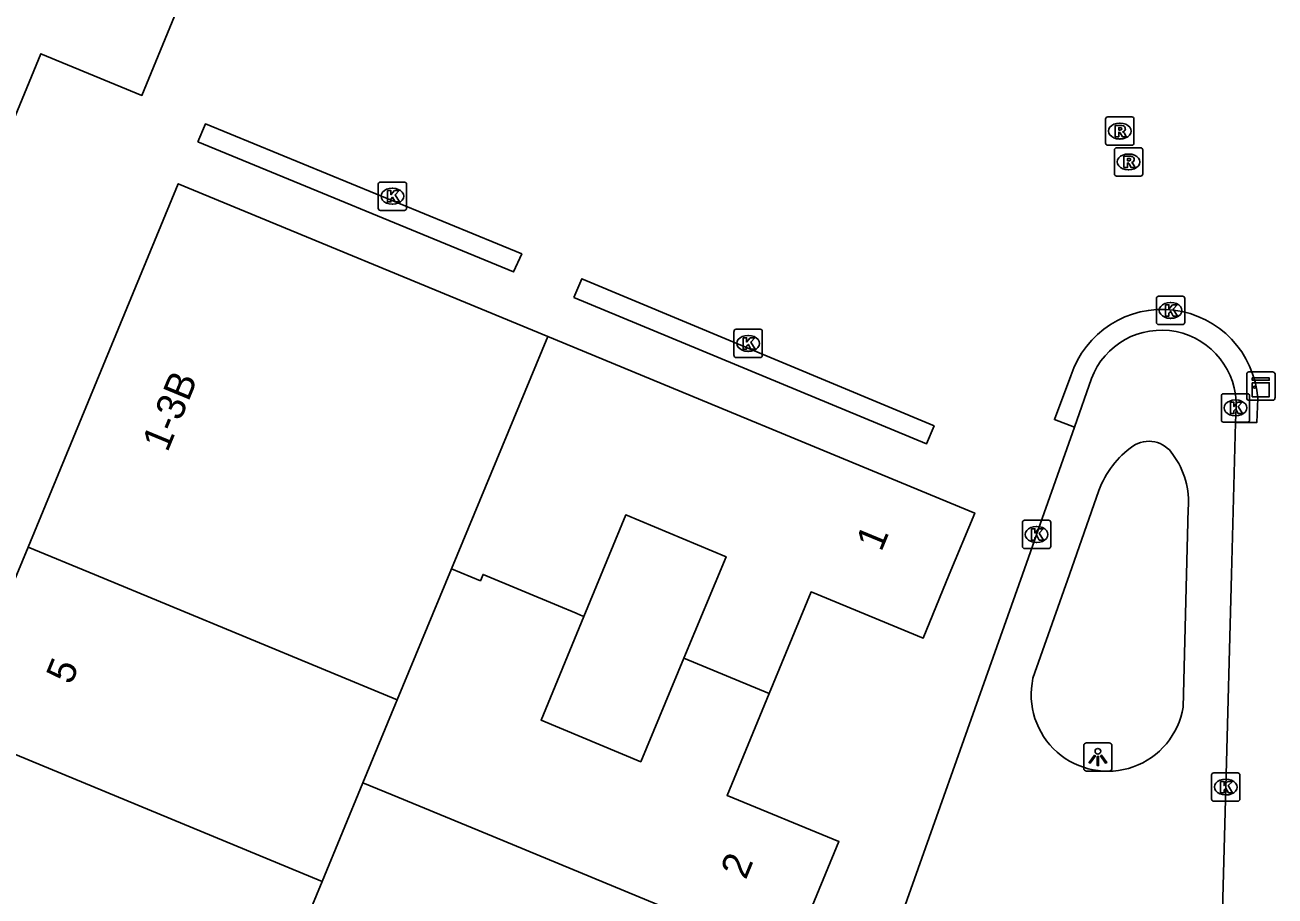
# Model space of a CAD drawing. Extents: x 160026 to 161302, y 384757 to 385701.
# Drawn here: x 160554.04 to 160598.24, y 384988.64 to 385019.42 of the extents above; entities that cross this region are included whole.
import ezdxf

# ---------------------------------------------------------------- set-up
doc = ezdxf.new("R2010")
doc.units = 0
for name, color, linetype in [('IMGEO_Haag', 7, 'Continuous'), ('IMGEO_Kast', 7, 'Continuous'), ('IMGEO_Kolk', 7, 'Continuous'), ('IMGEO_Lichtpunt', 7, 'Continuous'), ('IMGEO_Pand', 7, 'Continuous'), ('IMGEO_Pand_nummerreeks', 7, 'Continuous'), ('IMGEO_Rijbaan_lokaal_open', 7, 'Continuous'), ('IMGEO_Rioolput', 7, 'Continuous'), ('IMGEO_Voetpad_open', 7, 'Continuous')]:
    doc.layers.add(name, color=color, linetype=linetype)

msp = doc.modelspace()

# ---------------------------------------------------------------- linework, layer by layer
at = {"layer": 'IMGEO_Haag'}
for points in [[(160560.148, 385015.284), (160560.421, 385015.919), (160571.606, 385011.326), (160571.314, 385010.691), (160560.148, 385015.284)], [(160573.447, 385009.785), (160573.728, 385010.449), (160586.183, 385005.251), (160585.915, 385004.616), (160573.447, 385009.785)], [(160591.019, 385007.016), (160590.443, 385005.472), (160591.148, 385005.204)], [(160596.848, 385005.375), (160597.599, 385005.368), (160597.63, 385006.214)]]:
    msp.add_lwpolyline(points, dxfattribs=at)
msp.add_arc((160594.247, 385005.973), 3.392, 4.08, 162.0861, dxfattribs=at)
at = {"layer": 'IMGEO_Kast'}
for p, q in [((160597.242, 385006.232), (160597.242, 385007.073)), ((160597.242, 385007.073), (160597.242, 385006.232)), ((160597.317, 385007.157), (160598.158, 385007.157)), ((160598.158, 385007.157), (160597.317, 385007.157)), ((160598.242, 385007.082), (160598.242, 385006.241)), ((160598.242, 385006.241), (160598.242, 385007.082)), ((160598.167, 385006.157), (160597.326, 385006.157)), ((160597.326, 385006.157), (160598.167, 385006.157))]:
    msp.add_line(p, q, dxfattribs=at)
for points in [[(160597.437, 385006.947), (160598.037, 385006.947), (160598.037, 385006.862), (160597.437, 385006.862), (160597.437, 385006.947)], [(160597.437, 385006.772), (160598.037, 385006.772), (160598.037, 385006.283), (160597.437, 385006.283), (160597.437, 385006.772)]]:
    msp.add_lwpolyline(points, dxfattribs=at)
msp.add_circle((160597.521, 385006.621), 0.0377, dxfattribs=at)
for centre, start, end in [((160597.32, 385007.079), 92.4484, 184.2845), ((160597.32, 385007.079), 92.4484, 184.2845), ((160598.164, 385007.079), 2.4484, 94.2845), ((160598.164, 385007.079), 2.4484, 94.2845), ((160597.32, 385006.235), 182.4484, 274.2845), ((160597.32, 385006.235), 182.4484, 274.2845), ((160598.164, 385006.235), 272.4484, 4.2845), ((160598.164, 385006.235), 272.4484, 4.2845)]:
    msp.add_arc(centre, 0.0779, start, end, dxfattribs=at)
at = {"layer": 'IMGEO_Kolk'}
for p, q in [((160566.531, 385012.941), (160566.531, 385013.793)), ((160566.606, 385013.867), (160567.458, 385013.867)), ((160567.019, 385013.647), (160567.044, 385013.647)), ((160567.532, 385013.793), (160567.532, 385012.941)), ((160567.458, 385012.867), (160566.606, 385012.867)), ((160567.042, 385013.087), (160567.017, 385013.087)), ((160594.048, 385008.905), (160594.048, 385009.757)), ((160594.123, 385009.831), (160594.975, 385009.831)), ((160594.536, 385009.611), (160594.561, 385009.611)), ((160595.049, 385009.757), (160595.049, 385008.905)), ((160594.975, 385008.831), (160594.123, 385008.831)), ((160594.559, 385009.051), (160594.534, 385009.051)), ((160579.11, 385007.739), (160579.11, 385008.591)), ((160579.185, 385008.665), (160580.037, 385008.665)), ((160579.598, 385008.445), (160579.623, 385008.445)), ((160580.111, 385008.591), (160580.111, 385007.739)), ((160579.621, 385007.885), (160579.596, 385007.885)), ((160580.037, 385007.665), (160579.185, 385007.665)), ((160596.344, 385005.46), (160596.344, 385006.312)), ((160596.419, 385006.386), (160597.271, 385006.386)), ((160596.832, 385006.166), (160596.857, 385006.166)), ((160597.345, 385006.312), (160597.345, 385005.46)), ((160597.271, 385005.386), (160596.419, 385005.386)), ((160596.855, 385005.606), (160596.83, 385005.606)), ((160589.309, 385000.988), (160589.309, 385001.84)), ((160589.384, 385001.914), (160590.236, 385001.914)), ((160589.797, 385001.694), (160589.822, 385001.694)), ((160590.31, 385001.84), (160590.31, 385000.988)), ((160590.236, 385000.914), (160589.384, 385000.914)), ((160589.82, 385001.134), (160589.795, 385001.134)), ((160595.999, 384992.063), (160595.999, 384992.915)), ((160596.074, 384992.989), (160596.926, 384992.989)), ((160597, 384992.915), (160597, 384992.063)), ((160596.487, 384992.769), (160596.512, 384992.769)), ((160596.926, 384991.989), (160596.074, 384991.989)), ((160596.51, 384992.209), (160596.485, 384992.209))]:
    msp.add_line(p, q, dxfattribs=at)
for points in [[(160566.531, 385012.941), (160566.531, 385013.793)], [(160566.606, 385013.867), (160567.458, 385013.867)], [(160567.532, 385013.793), (160567.532, 385012.941)], [(160566.852, 385013.567), (160566.975, 385013.567), (160566.975, 385013.416), (160567.105, 385013.567), (160567.269, 385013.567), (160567.123, 385013.416), (160567.276, 385013.167), (160567.124, 385013.167), (160567.039, 385013.331), (160566.975, 385013.264), (160566.975, 385013.167), (160566.852, 385013.167), (160566.852, 385013.567)], [(160567.458, 385012.867), (160566.606, 385012.867)], [(160594.048, 385008.905), (160594.048, 385009.757)], [(160594.123, 385009.831), (160594.975, 385009.831)], [(160595.049, 385009.757), (160595.049, 385008.905)], [(160594.369, 385009.531), (160594.492, 385009.531), (160594.492, 385009.38), (160594.622, 385009.531), (160594.786, 385009.531), (160594.64, 385009.38), (160594.793, 385009.131), (160594.641, 385009.131), (160594.556, 385009.295), (160594.492, 385009.228), (160594.492, 385009.131), (160594.369, 385009.131), (160594.369, 385009.531)], [(160594.975, 385008.831), (160594.123, 385008.831)], [(160579.11, 385007.739), (160579.11, 385008.591)], [(160579.185, 385008.665), (160580.037, 385008.665)], [(160579.431, 385008.365), (160579.554, 385008.365), (160579.554, 385008.214), (160579.684, 385008.365), (160579.848, 385008.365), (160579.702, 385008.214), (160579.855, 385007.965), (160579.703, 385007.965), (160579.618, 385008.129), (160579.554, 385008.062), (160579.554, 385007.965), (160579.431, 385007.965), (160579.431, 385008.365)], [(160580.111, 385008.591), (160580.111, 385007.739)], [(160580.037, 385007.665), (160579.185, 385007.665)], [(160596.344, 385005.46), (160596.344, 385006.312)], [(160596.419, 385006.386), (160597.271, 385006.386)], [(160596.665, 385006.086), (160596.788, 385006.086), (160596.788, 385005.935), (160596.918, 385006.086), (160597.082, 385006.086), (160596.936, 385005.935), (160597.089, 385005.686), (160596.937, 385005.686), (160596.852, 385005.85), (160596.788, 385005.783), (160596.788, 385005.686), (160596.665, 385005.686), (160596.665, 385006.086)], [(160597.345, 385006.312), (160597.345, 385005.46)], [(160597.271, 385005.386), (160596.419, 385005.386)], [(160589.309, 385000.988), (160589.309, 385001.84)], [(160589.384, 385001.914), (160590.236, 385001.914)], [(160590.31, 385001.84), (160590.31, 385000.988)], [(160589.63, 385001.614), (160589.753, 385001.614), (160589.753, 385001.463), (160589.883, 385001.614), (160590.047, 385001.614), (160589.901, 385001.463), (160590.054, 385001.214), (160589.902, 385001.214), (160589.817, 385001.378), (160589.753, 385001.311), (160589.753, 385001.214), (160589.63, 385001.214), (160589.63, 385001.614)], [(160590.236, 385000.914), (160589.384, 385000.914)], [(160595.999, 384992.063), (160595.999, 384992.915)], [(160596.074, 384992.989), (160596.926, 384992.989)], [(160597, 384992.915), (160597, 384992.063)], [(160596.32, 384992.689), (160596.443, 384992.689), (160596.443, 384992.538), (160596.573, 384992.689), (160596.737, 384992.689), (160596.591, 384992.538), (160596.744, 384992.289), (160596.592, 384992.289), (160596.507, 384992.453), (160596.443, 384992.386), (160596.443, 384992.289), (160596.32, 384992.289), (160596.32, 384992.689)], [(160596.926, 384991.989), (160596.074, 384991.989)]]:
    msp.add_lwpolyline(points, dxfattribs=at)
for centre, start, end in [((160566.608, 385013.791), 91.552, 178.448), ((160566.608, 385013.791), 91.552, 178.448), ((160567.456, 385013.791), 1.552, 88.448), ((160567.456, 385013.791), 1.552, 88.448), ((160566.608, 385012.943), 181.552, 268.448), ((160566.608, 385012.943), 181.552, 268.448), ((160567.456, 385012.943), 271.552, 358.448), ((160567.456, 385012.943), 271.552, 358.448), ((160594.125, 385009.755), 91.552, 178.448), ((160594.125, 385009.755), 91.552, 178.448), ((160594.973, 385009.755), 1.552, 88.448), ((160594.973, 385009.755), 1.552, 88.448), ((160594.125, 385008.907), 181.552, 268.448), ((160594.125, 385008.907), 181.552, 268.448), ((160594.973, 385008.907), 271.552, 358.448), ((160594.973, 385008.907), 271.552, 358.448), ((160579.187, 385008.589), 91.552, 178.448), ((160579.187, 385008.589), 91.552, 178.448), ((160580.035, 385008.589), 1.552, 88.448), ((160580.035, 385008.589), 1.552, 88.448), ((160579.187, 385007.741), 181.552, 268.448), ((160579.187, 385007.741), 181.552, 268.448), ((160580.035, 385007.741), 271.552, 358.448), ((160580.035, 385007.741), 271.552, 358.448), ((160596.421, 385006.31), 91.552, 178.448), ((160596.421, 385006.31), 91.552, 178.448), ((160597.269, 385006.31), 1.552, 88.448), ((160597.269, 385006.31), 1.552, 88.448), ((160596.421, 385005.462), 181.552, 268.448), ((160596.421, 385005.462), 181.552, 268.448), ((160597.269, 385005.462), 271.552, 358.448), ((160597.269, 385005.462), 271.552, 358.448), ((160589.386, 385001.838), 91.552, 178.448), ((160589.386, 385001.838), 91.552, 178.448), ((160590.234, 385001.838), 1.552, 88.448), ((160590.234, 385001.838), 1.552, 88.448), ((160589.386, 385000.99), 181.552, 268.448), ((160589.386, 385000.99), 181.552, 268.448), ((160590.234, 385000.99), 271.552, 358.448), ((160590.234, 385000.99), 271.552, 358.448), ((160596.076, 384992.913), 91.552, 178.448), ((160596.076, 384992.913), 91.552, 178.448), ((160596.924, 384992.913), 1.552, 88.448), ((160596.924, 384992.913), 1.552, 88.448), ((160596.076, 384992.065), 181.552, 268.448), ((160596.076, 384992.065), 181.552, 268.448), ((160596.924, 384992.065), 271.552, 358.448), ((160596.924, 384992.065), 271.552, 358.448)]:
    msp.add_arc(centre, 0.0765, start, end, dxfattribs=at)
for centre, major_axis, ratio, start_param, end_param in [((160567.018, 385013.367), (-0.387, 0.002), 0.722429, 4.712389, 7.853982), ((160567.043, 385013.367), (-0.39, 0.002), 0.717154, 1.570796, 4.712389), ((160594.535, 385009.331), (-0.387, 0.002), 0.722429, 4.712389, 7.853982), ((160594.56, 385009.331), (-0.39, 0.002), 0.717154, 1.570796, 4.712389), ((160579.597, 385008.165), (-0.387, 0.002), 0.722429, 4.712389, 7.853982), ((160579.622, 385008.165), (-0.39, 0.002), 0.717154, 1.570796, 4.712389), ((160596.831, 385005.886), (-0.387, 0.002), 0.722429, 4.712389, 7.853982), ((160596.856, 385005.886), (-0.39, 0.002), 0.717154, 1.570796, 4.712389), ((160589.796, 385001.414), (-0.387, 0.002), 0.722429, 4.712389, 7.853982), ((160589.821, 385001.414), (-0.39, 0.002), 0.717154, 1.570796, 4.712389), ((160596.486, 384992.489), (-0.387, 0.002), 0.722429, 4.712389, 7.853982), ((160596.511, 384992.489), (-0.39, 0.002), 0.717154, 1.570796, 4.712389)]:
    msp.add_ellipse(centre, major_axis=major_axis, ratio=ratio, start_param=start_param, end_param=end_param, dxfattribs=at)
at = {"layer": 'IMGEO_Lichtpunt'}
for p, q in [((160591.479, 384993.954), (160591.479, 384993.147)), ((160591.479, 384993.954), (160591.479, 384993.147)), ((160592.381, 384994.049), (160591.573, 384994.049)), ((160592.381, 384994.049), (160591.573, 384994.049)), ((160592.475, 384993.147), (160592.475, 384993.954)), ((160592.475, 384993.147), (160592.475, 384993.954)), ((160591.573, 384993.053), (160592.381, 384993.053)), ((160591.573, 384993.053), (160592.381, 384993.053))]:
    msp.add_line(p, q, dxfattribs=at)
for points in [[(160591.853, 384993.618), (160591.892, 384993.59), (160591.704, 384993.328), (160591.666, 384993.355), (160591.853, 384993.618)], [(160591.955, 384993.57), (160592.002, 384993.57), (160592.002, 384993.248), (160591.955, 384993.248), (160591.955, 384993.57)], [(160592.065, 384993.59), (160592.103, 384993.617), (160592.29, 384993.355), (160592.251, 384993.327), (160592.065, 384993.59)]]:
    msp.add_lwpolyline(points, dxfattribs=at)
msp.add_circle((160591.978, 384993.752), 0.0994, dxfattribs=at)
for centre, start, end in [((160591.573, 384993.954), 90, 180), ((160591.573, 384993.954), 90, 180), ((160592.381, 384993.954), 0, 90), ((160592.381, 384993.954), 0, 90), ((160591.573, 384993.147), 180, 270), ((160591.573, 384993.147), 180, 270), ((160592.381, 384993.147), 270, 0), ((160592.381, 384993.147), 270, 360)]:
    msp.add_arc(centre, 0.0946, start, end, dxfattribs=at)
at = {"layer": 'IMGEO_Pand'}
for points in [[(160572.529, 385008.408), (160559.46, 385013.809), (160554.149, 385000.967)], [(160569.125, 385000.202), (160572.529, 385008.408)], [(160580.352, 384995.789), (160581.839, 384999.384), (160585.794, 384997.749), (160586.725, 385000), (160587.622, 385002.171), (160572.529, 385008.408)], [(160577.338, 384997.044), (160578.83, 385000.628), (160575.284, 385002.104), (160573.802, 384998.516)], [(160554.149, 385000.967), (160553.749, 385000), (160551.494, 384994.546)], [(160554.149, 385000.967), (160556.49, 385000), (160567.202, 384995.573)], [(160567.202, 384995.573), (160569.125, 385000.202)], [(160573.802, 384998.516), (160573.678, 384998.567), (160573.528, 384998.63), (160572.91, 384998.887), (160570.237, 385000), (160570.145, 384999.777), (160569.125, 385000.202)], [(160573.802, 384998.516), (160572.29, 384994.853), (160575.815, 384993.385), (160577.338, 384997.044)], [(160580.352, 384995.789), (160577.338, 384997.044)], [(160565.99, 384992.641), (160567.143, 384995.431), (160567.202, 384995.573)], [(160581.101, 384986.4), (160582.82, 384990.559), (160578.865, 384992.194), (160580.352, 384995.789)], [(160551.494, 384994.546), (160564.547, 384989.152)], [(160564.547, 384989.152), (160565.99, 384992.641)], [(160565.99, 384992.641), (160567.018, 384992.216), (160570.591, 384990.74), (160581.101, 384986.4)], [(160562.781, 384984.881), (160564.547, 384989.152)]]:
    msp.add_lwpolyline(points, dxfattribs=at)
at = {"layer": 'IMGEO_Rijbaan_lokaal_open'}
for points in [[(160591.751, 385006.921), (160591.148, 385005.204)], [(160596.848, 385005.375), (160596.865, 385005.886)], [(160591.148, 385005.204), (160589.809, 385001.415), (160589.803, 385001.397), (160589.307, 385000), (160584.068, 384985.227), (160578.447, 384969.326), (160572.864, 384953.481), (160571.348, 384949.206), (160570.707, 384947.39)], [(160594.882, 384927.993), (160594.871, 384929.668), (160595.391, 384949.601), (160595.933, 384971.552), (160596.501, 384992.49), (160596.703, 385000), (160596.799, 385003.576), (160596.848, 385005.375)], [(160589.682, 384996.333), (160590.972, 385000), (160592.015, 385002.963)], [(160595.176, 385002.317), (160595.115, 385000), (160594.993, 384995.31)]]:
    msp.add_lwpolyline(points, dxfattribs=at)
for centre, radius, start, end in [((160594.224, 385005.99), 2.643, 357.7478, 159.3696), ((160595.117, 385001.842), 3.298, 125.1689, 160.1312), ((160593.778, 385003.691), 1.016, 32.7954, 123.4967), ((160592.282, 385002.538), 2.902, 355.6399, 35.936), ((160592.324, 384995.752), 2.705, 167.6046, 350.5899)]:
    msp.add_arc(centre, radius, start, end, dxfattribs=at)
at = {"layer": 'IMGEO_Rioolput'}
for p, q in [((160592.253, 385015.242), (160592.253, 385016.094)), ((160592.328, 385016.168), (160593.18, 385016.168)), ((160592.741, 385015.948), (160592.766, 385015.948)), ((160593.254, 385016.094), (160593.254, 385015.242)), ((160592.764, 385015.388), (160592.739, 385015.388)), ((160593.18, 385015.168), (160592.328, 385015.168)), ((160592.563, 385014.152), (160592.563, 385015.004)), ((160592.638, 385015.078), (160593.49, 385015.078)), ((160593.564, 385015.004), (160593.564, 385014.152)), ((160593.051, 385014.858), (160593.076, 385014.858)), ((160593.49, 385014.078), (160592.638, 385014.078)), ((160593.074, 385014.298), (160593.049, 385014.298))]:
    msp.add_line(p, q, dxfattribs=at)
for points in [[(160592.253, 385015.242), (160592.253, 385016.094)], [(160592.328, 385016.168), (160593.18, 385016.168)], [(160592.842, 385015.866), (160592.59, 385015.868), (160592.59, 385015.468)], [(160593.254, 385016.094), (160593.254, 385015.242)], [(160592.59, 385015.468), (160592.714, 385015.468), (160592.714, 385015.63), (160592.725, 385015.63)], [(160592.768, 385015.787), (160592.714, 385015.787), (160592.714, 385015.706)], [(160592.714, 385015.706), (160592.766, 385015.706)], [(160592.772, 385015.601), (160592.843, 385015.468), (160592.983, 385015.468), (160592.918, 385015.594)], [(160593.18, 385015.168), (160592.328, 385015.168)], [(160592.563, 385014.152), (160592.563, 385015.004)], [(160592.638, 385015.078), (160593.49, 385015.078)], [(160593.564, 385015.004), (160593.564, 385014.152)], [(160593.152, 385014.776), (160592.9, 385014.778), (160592.9, 385014.378)], [(160592.9, 385014.378), (160593.024, 385014.378), (160593.024, 385014.54), (160593.035, 385014.54)], [(160593.078, 385014.697), (160593.024, 385014.697), (160593.024, 385014.616)], [(160593.024, 385014.616), (160593.076, 385014.616)], [(160593.082, 385014.511), (160593.153, 385014.378), (160593.293, 385014.378), (160593.228, 385014.504)], [(160593.49, 385014.078), (160592.638, 385014.078)]]:
    msp.add_lwpolyline(points, dxfattribs=at)
for centre, radius, start, end in [((160592.33, 385016.092), 0.0765, 91.552, 178.448), ((160592.33, 385016.092), 0.0765, 91.552, 178.448), ((160592.841, 385015.756), 0.109, 350.3612, 89.416), ((160593.178, 385016.092), 0.0765, 1.552, 88.448), ((160593.178, 385016.092), 0.0765, 1.552, 88.448), ((160592.724, 385015.577), 0.0533, 26.0293, 88.6989), ((160592.75, 385015.895), 0.19, 274.7715, 282.9687), ((160592.774, 385015.691), 0.0964, 77.0061, 93.1865), ((160592.788, 385015.748), 0.0378, 276.6634, 79.6772), ((160592.839, 385015.756), 0.112, 277.5842, 350.9817), ((160592.823, 385015.541), 0.108, 29.5134, 73.7905), ((160592.33, 385015.244), 0.0765, 181.552, 268.448), ((160592.33, 385015.244), 0.0765, 181.552, 268.448), ((160592.64, 385015.002), 0.0765, 91.552, 178.448), ((160592.64, 385015.002), 0.0765, 91.552, 178.448), ((160593.178, 385015.244), 0.0765, 271.552, 358.448), ((160593.178, 385015.244), 0.0765, 271.552, 358.448), ((160593.488, 385015.002), 0.0765, 1.552, 88.448), ((160593.488, 385015.002), 0.0765, 1.552, 88.448), ((160593.034, 385014.487), 0.0533, 26.0293, 88.6989), ((160593.06, 385014.805), 0.19, 274.7715, 282.9687), ((160593.084, 385014.601), 0.0964, 77.0061, 93.1865), ((160593.098, 385014.658), 0.0378, 276.6634, 79.6772), ((160593.151, 385014.666), 0.109, 350.3612, 89.416), ((160593.149, 385014.666), 0.112, 277.5842, 350.9817), ((160593.133, 385014.451), 0.108, 29.5134, 73.7905), ((160592.64, 385014.154), 0.0765, 181.552, 268.448), ((160592.64, 385014.154), 0.0765, 181.552, 268.448), ((160593.488, 385014.154), 0.0765, 271.552, 358.448), ((160593.488, 385014.154), 0.0765, 271.552, 358.448)]:
    msp.add_arc(centre, radius, start, end, dxfattribs=at)
for centre, major_axis, ratio, start_param, end_param in [((160592.74, 385015.668), (-0.387, 0.002), 0.722429, 4.712389, 7.853982), ((160592.765, 385015.668), (-0.39, 0.002), 0.717154, 1.570796, 4.712389), ((160593.05, 385014.578), (-0.387, 0.002), 0.722429, 4.712389, 7.853982), ((160593.075, 385014.578), (-0.39, 0.002), 0.717154, 1.570796, 4.712389)]:
    msp.add_ellipse(centre, major_axis=major_axis, ratio=ratio, start_param=start_param, end_param=end_param, dxfattribs=at)
at = {"layer": 'IMGEO_Voetpad_open'}
msp.add_lwpolyline([(160512.105, 384915.262), (160522.539, 384940.554), (160533.821, 384967.876), (160547.007, 385000), (160554.593, 385018.402), (160558.17, 385016.931), (160561.06, 385023.947), (160557.56, 385025.42), (160559.171, 385029.51), (160560.795, 385034.884)], dxfattribs=at)

# ---------------------------------------------------------------- texts
at = {"layer": 'IMGEO_Pand_nummerreeks'}
for s, rotation, p in [('1-3B', 67.5345, (160559.074, 385004.293)), ('1', 67.5403, (160584.318, 385000.774)), ('5', 67.5345, (160555.674, 384996.071)), ('2', 67.546, (160579.526, 384989.186))]:
    msp.add_text(s, height=1, rotation=rotation, dxfattribs=at).set_placement(p)

doc.saveas('drawing.dxf')
